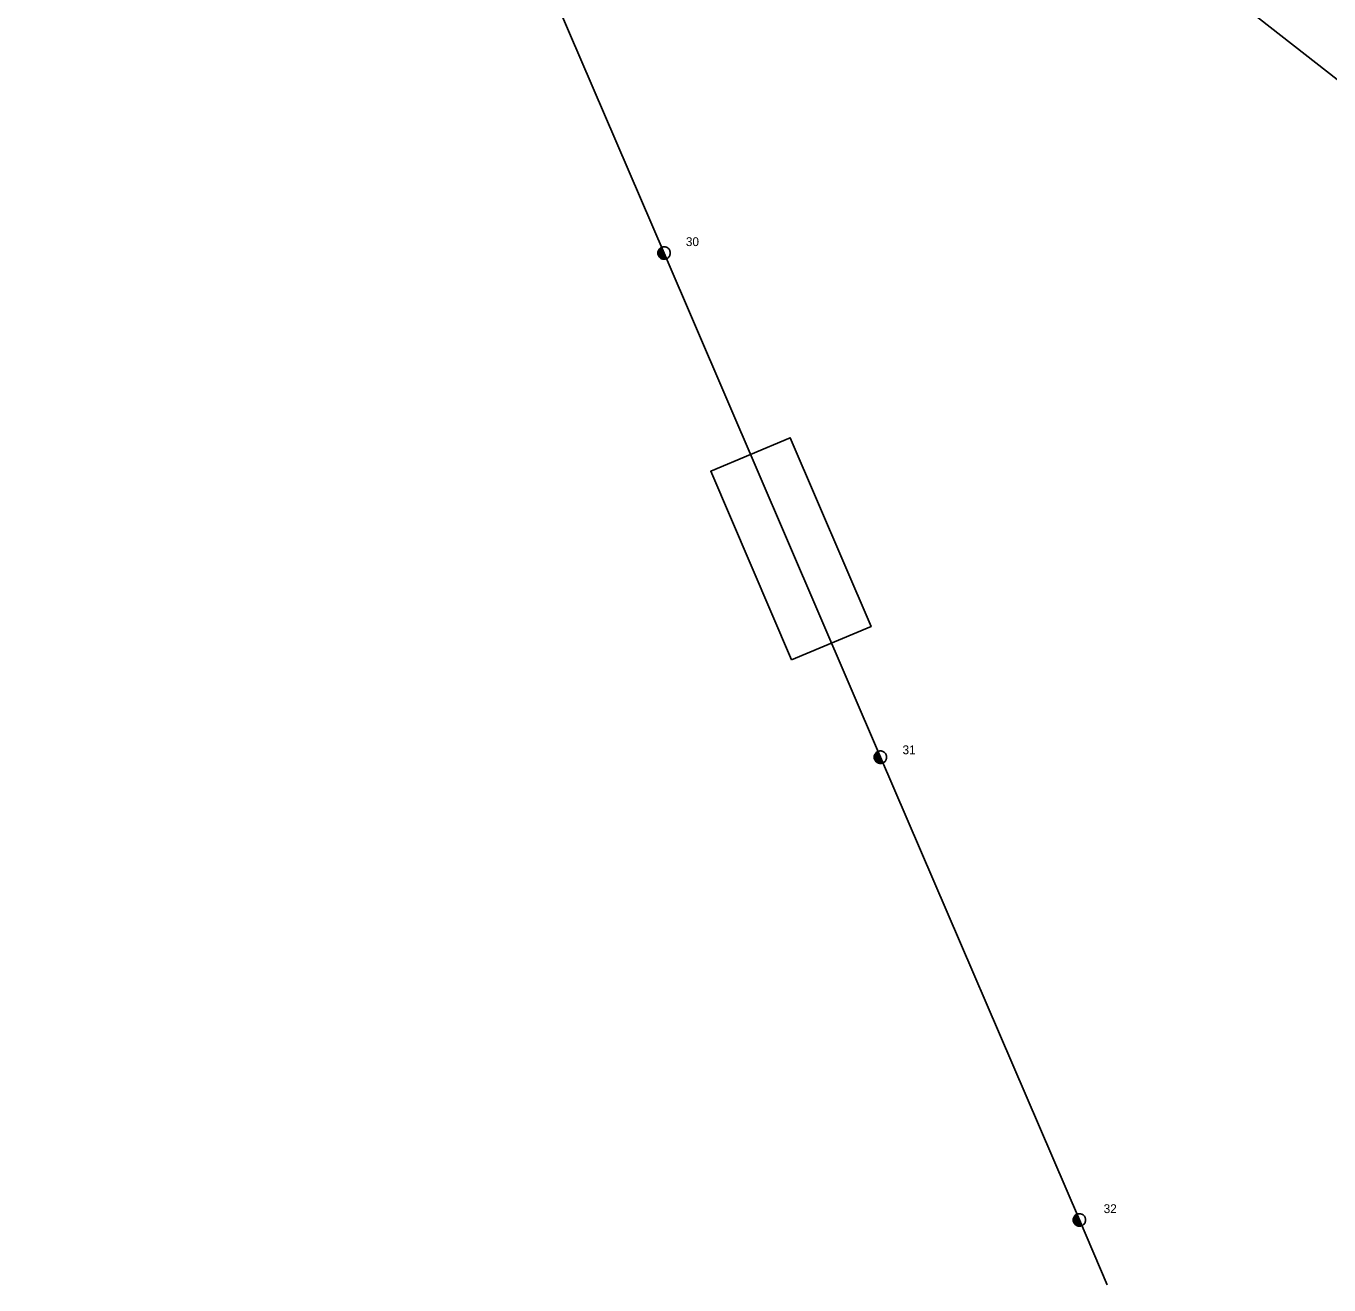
# Model space of a CAD drawing. Extents: x -761250 to -760338, y -1155000 to -1154503.
# Drawn here: x -761250 to -760993.1, y -1155000 to -1154751.7 of the extents above; entities that cross this region are included whole.
import ezdxf

# ---------------------------------------------------------------- set-up
doc = ezdxf.new("R2010")
doc.units = 0
for name, color, linetype in [('Vrstva 1', 7, 'Continuous'), ('Vrstva 13', 7, 'Continuous'), ('Vrstva 14', 7, 'Continuous'), ('Vrstva 35', 7, 'Continuous')]:
    doc.layers.add(name, color=color, linetype=linetype)

msp = doc.modelspace()

# ---------------------------------------------------------------- linework, layer by layer
at = {"layer": 'Vrstva 1'}
for points in [[(-761250, -1154503.48), (-761238.83, -1154529.58), (-761200.5, -1154618.7), (-761164.12, -1154703.56), (-761124.2, -1154796.5), (-761081.55, -1154895.93), (-761042.31, -1154987.19), (-761036.84, -1155000)], [(-761250, -1154560.04), (-761239.44, -1154568.33), (-761186.98, -1154609.48), (-761124.95, -1154658.28), (-761056.6, -1154711.35), (-760986.69, -1154766.03), (-760934.04, -1154806.89), (-760877.08, -1154825.6), (-760813.81, -1154846.09), (-760723.01, -1154875.68), (-760629.06, -1154906.1), (-760533.78, -1154936.84), (-760468.16, -1154958.01), (-760403.99, -1154978.73), (-760337.85, -1155000)]]:
    msp.add_lwpolyline(points, dxfattribs=at)
at = {"layer": 'Vrstva 13'}
for points in [[(-761123.707, -1154797.615), (-761123.592, -1154797.557), (-761123.485, -1154797.487), (-761123.385, -1154797.406), (-761123.294, -1154797.315), (-761123.213, -1154797.215), (-761123.143, -1154797.107), (-761123.085, -1154796.993), (-761123.038, -1154796.873), (-761123.005, -1154796.749), (-761122.985, -1154796.621), (-761122.978, -1154796.493), (-761122.985, -1154796.365), (-761123.005, -1154796.238), (-761123.038, -1154796.113), (-761123.085, -1154795.993), (-761123.143, -1154795.879), (-761123.213, -1154795.771), (-761123.294, -1154795.671), (-761123.385, -1154795.58), (-761123.485, -1154795.499), (-761123.592, -1154795.429), (-761123.707, -1154795.371), (-761123.827, -1154795.325), (-761123.952, -1154795.292), (-761124.078, -1154795.272), (-761124.206, -1154795.265), (-761124.335, -1154795.271), (-761124.462, -1154795.292), (-761124.586, -1154795.325), (-761124.706, -1154795.371), (-761124.821, -1154795.429), (-761124.929, -1154795.499), (-761125.029, -1154795.58), (-761125.12, -1154795.672), (-761125.2, -1154795.771), (-761125.27, -1154795.879), (-761125.329, -1154795.993), (-761125.375, -1154796.114), (-761125.408, -1154796.238), (-761125.429, -1154796.365), (-761125.435, -1154796.493), (-761125.428, -1154796.621), (-761125.408, -1154796.748), (-761125.375, -1154796.873), (-761125.329, -1154796.993), (-761125.271, -1154797.107), (-761125.201, -1154797.215), (-761125.119, -1154797.315), (-761125.029, -1154797.406), (-761124.929, -1154797.487), (-761124.821, -1154797.557), (-761124.706, -1154797.616), (-761124.586, -1154797.661), (-761124.462, -1154797.694), (-761124.335, -1154797.715), (-761124.207, -1154797.722), (-761124.078, -1154797.715), (-761123.951, -1154797.694), (-761123.827, -1154797.661), (-761123.707, -1154797.615)], [(-761125.339, -1154796.195), (-761124.762, -1154797.492)], [(-761125.185, -1154795.832), (-761124.381, -1154797.638)], [(-761124.993, -1154795.558), (-761124.064, -1154797.644)], [(-761124.701, -1154795.365), (-761123.702, -1154797.609)], [(-761081.057, -1154897.045), (-761080.942, -1154896.987), (-761080.835, -1154896.917), (-761080.735, -1154896.836), (-761080.644, -1154896.745), (-761080.563, -1154896.645), (-761080.493, -1154896.537), (-761080.435, -1154896.423), (-761080.388, -1154896.303), (-761080.355, -1154896.179), (-761080.335, -1154896.051), (-761080.328, -1154895.923), (-761080.335, -1154895.795), (-761080.355, -1154895.668), (-761080.388, -1154895.544), (-761080.435, -1154895.423), (-761080.493, -1154895.309), (-761080.563, -1154895.201), (-761080.644, -1154895.101), (-761080.734, -1154895.01), (-761080.834, -1154894.929), (-761080.942, -1154894.859), (-761081.057, -1154894.801), (-761081.177, -1154894.755), (-761081.301, -1154894.722), (-761081.428, -1154894.702), (-761081.556, -1154894.695), (-761081.685, -1154894.701), (-761081.812, -1154894.722), (-761081.936, -1154894.755), (-761082.056, -1154894.801), (-761082.171, -1154894.859), (-761082.279, -1154894.929), (-761082.379, -1154895.01), (-761082.47, -1154895.102), (-761082.55, -1154895.201), (-761082.62, -1154895.309), (-761082.679, -1154895.423), (-761082.725, -1154895.544), (-761082.758, -1154895.668), (-761082.779, -1154895.795), (-761082.785, -1154895.923), (-761082.778, -1154896.051), (-761082.758, -1154896.178), (-761082.725, -1154896.303), (-761082.679, -1154896.423), (-761082.621, -1154896.537), (-761082.55, -1154896.645), (-761082.469, -1154896.745), (-761082.379, -1154896.836), (-761082.279, -1154896.917), (-761082.171, -1154896.987), (-761082.056, -1154897.046), (-761081.936, -1154897.091), (-761081.812, -1154897.124), (-761081.685, -1154897.145), (-761081.557, -1154897.152), (-761081.428, -1154897.145), (-761081.301, -1154897.124), (-761081.177, -1154897.091), (-761081.057, -1154897.045)], [(-761082.535, -1154895.262), (-761081.731, -1154897.068)], [(-761082.343, -1154894.988), (-761081.414, -1154897.074)], [(-761082.051, -1154894.795), (-761081.052, -1154897.039)], [(-761082.689, -1154895.625), (-761082.112, -1154896.922)], [(-761041.817, -1154988.305), (-761041.702, -1154988.247), (-761041.595, -1154988.177), (-761041.495, -1154988.096), (-761041.403, -1154988.005), (-761041.323, -1154987.906), (-761041.253, -1154987.798), (-761041.194, -1154987.683), (-761041.148, -1154987.563), (-761041.115, -1154987.439), (-761041.095, -1154987.312), (-761041.088, -1154987.183), (-761041.095, -1154987.055), (-761041.115, -1154986.928), (-761041.148, -1154986.804), (-761041.194, -1154986.684), (-761041.253, -1154986.57), (-761041.323, -1154986.461), (-761041.404, -1154986.361), (-761041.494, -1154986.271), (-761041.594, -1154986.19), (-761041.702, -1154986.12), (-761041.817, -1154986.061), (-761041.937, -1154986.015), (-761042.061, -1154985.982), (-761042.188, -1154985.962), (-761042.316, -1154985.955), (-761042.445, -1154985.962), (-761042.572, -1154985.982), (-761042.696, -1154986.015), (-761042.816, -1154986.061), (-761042.931, -1154986.12), (-761043.038, -1154986.19), (-761043.139, -1154986.271), (-761043.229, -1154986.362), (-761043.31, -1154986.462), (-761043.38, -1154986.569), (-761043.439, -1154986.684), (-761043.485, -1154986.804), (-761043.518, -1154986.928), (-761043.538, -1154987.055), (-761043.545, -1154987.184), (-761043.538, -1154987.312), (-761043.518, -1154987.439), (-761043.485, -1154987.563), (-761043.439, -1154987.683), (-761043.38, -1154987.798), (-761043.31, -1154987.905), (-761043.229, -1154988.005), (-761043.139, -1154988.096), (-761043.039, -1154988.177), (-761042.931, -1154988.248), (-761042.816, -1154988.306), (-761042.696, -1154988.352), (-761042.572, -1154988.385), (-761042.445, -1154988.405), (-761042.317, -1154988.412), (-761042.188, -1154988.405), (-761042.061, -1154988.385), (-761041.937, -1154988.352), (-761041.817, -1154988.305)], [(-761043.449, -1154986.886), (-761042.871, -1154988.183)], [(-761043.295, -1154986.523), (-761042.491, -1154988.329)], [(-761043.102, -1154986.248), (-761042.173, -1154988.334)], [(-761042.811, -1154986.055), (-761041.811, -1154988.299)]]:
    msp.add_lwpolyline(points, dxfattribs=at)
at = {"layer": 'Vrstva 35'}
msp.add_lwpolyline([(-761099.06, -1154876.74), (-761083.38, -1154870.16), (-761099.32, -1154832.94), (-761114.99, -1154839.52)], close=True, dxfattribs=at)

# ---------------------------------------------------------------- texts
at = {"layer": 'Vrstva 14'}
for s, p in [('30', (-761119.91, -1154795.13)), ('31', (-761077.19, -1154895.34)), ('32', (-761037.54, -1154985.83))]:
    msp.add_text(s, height=1.74, dxfattribs=at).set_placement(p)

doc.saveas('drawing.dxf')
